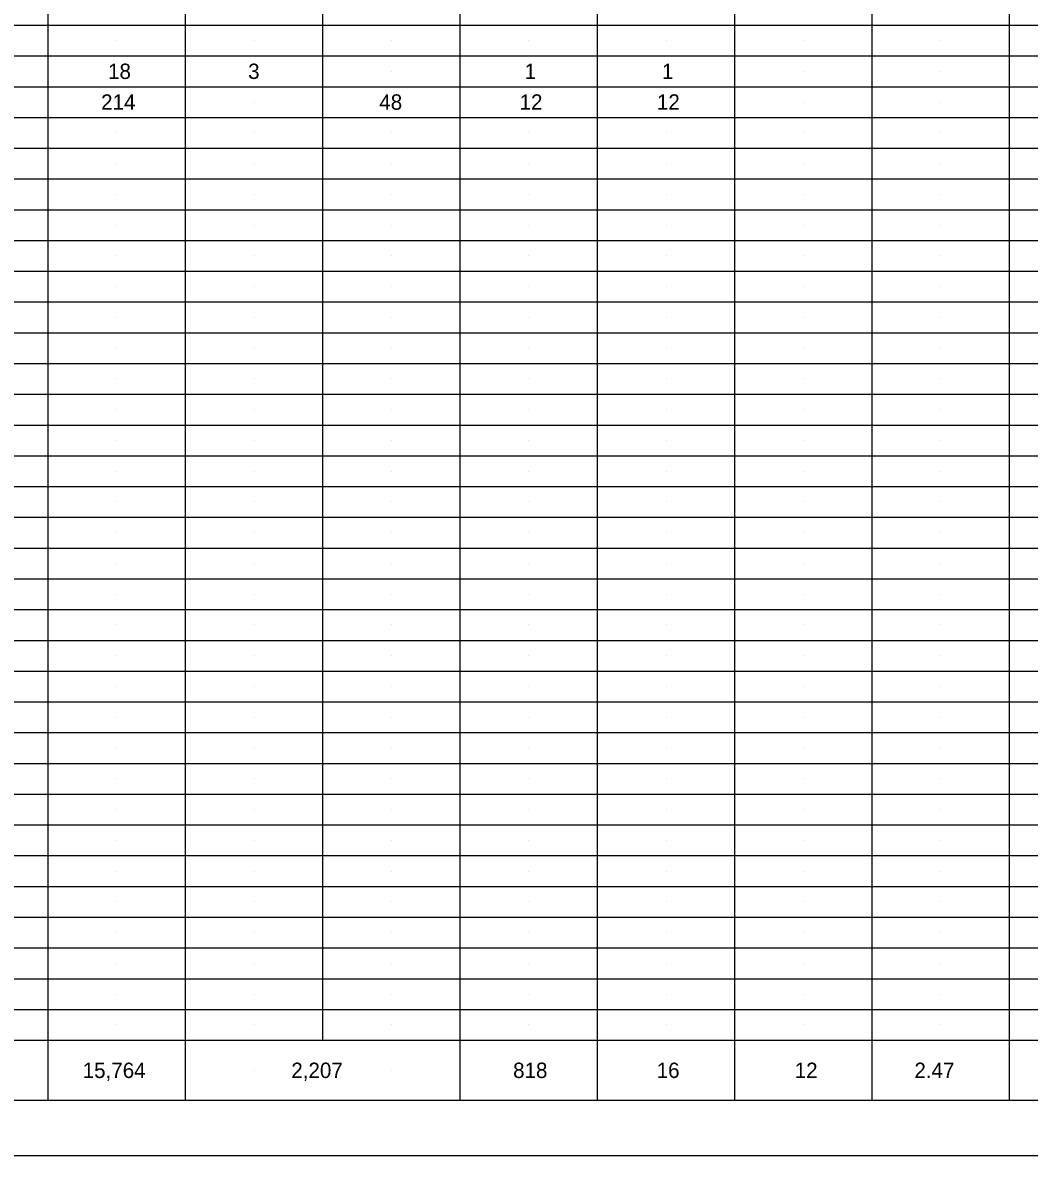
# Model space of a CAD drawing. Extents: x 2107022.8 to 2107056.8, y 706071 to 706093.
# Drawn here: x 2107038.83 to 2107047.99, y 706070.99 to 706081.3 of the extents above; entities that cross this region are included whole.
import ezdxf

# ---------------------------------------------------------------- set-up
doc = ezdxf.new("R2010")
doc.units = 0
for name, color, linetype in [('SC_Scratch1', 7, 'Continuous'), ('SH_Border', 7, 'Continuous'), ('SH_Cut_Line', 7, 'Continuous'), ('SH_Data', 7, 'Continuous'), ('SH_Text', 7, 'Continuous')]:
    doc.layers.add(name, color=color, linetype=linetype)

msp = doc.modelspace()

# ---------------------------------------------------------------- linework, layer by layer
at = {"layer": 'SC_Scratch1'}
for p, q in [((2107039.687, 706081.135), (2107039.687, 706081.135)), ((2107040.937, 706081.135), (2107040.937, 706081.135)), ((2107042.187, 706081.135), (2107042.187, 706081.135)), ((2107043.437, 706081.135), (2107043.437, 706081.135)), ((2107044.687, 706081.135), (2107044.687, 706081.135)), ((2107045.937, 706081.135), (2107045.937, 706081.135)), ((2107047.187, 706081.135), (2107047.187, 706081.135)), ((2107039.687, 706080.855), (2107039.687, 706080.855)), ((2107040.937, 706080.855), (2107040.937, 706080.855)), ((2107042.187, 706080.855), (2107042.187, 706080.855)), ((2107043.437, 706080.855), (2107043.437, 706080.855)), ((2107044.687, 706080.855), (2107044.687, 706080.855)), ((2107045.937, 706080.855), (2107045.937, 706080.855)), ((2107047.187, 706080.855), (2107047.187, 706080.855)), ((2107039.687, 706080.575), (2107039.687, 706080.575)), ((2107040.937, 706080.575), (2107040.937, 706080.575)), ((2107042.187, 706080.575), (2107042.187, 706080.575)), ((2107043.437, 706080.575), (2107043.437, 706080.575)), ((2107044.687, 706080.575), (2107044.687, 706080.575)), ((2107045.937, 706080.575), (2107045.937, 706080.575)), ((2107047.187, 706080.575), (2107047.187, 706080.575)), ((2107039.687, 706080.295), (2107039.687, 706080.295)), ((2107040.937, 706080.295), (2107040.937, 706080.295)), ((2107042.187, 706080.295), (2107042.187, 706080.295)), ((2107043.437, 706080.295), (2107043.437, 706080.295)), ((2107044.687, 706080.295), (2107044.687, 706080.295)), ((2107045.937, 706080.295), (2107045.937, 706080.295)), ((2107047.187, 706080.295), (2107047.187, 706080.295)), ((2107039.687, 706080.015), (2107039.687, 706080.015)), ((2107040.937, 706080.015), (2107040.937, 706080.015)), ((2107042.187, 706080.015), (2107042.187, 706080.015)), ((2107043.437, 706080.015), (2107043.437, 706080.015)), ((2107044.687, 706080.015), (2107044.687, 706080.015)), ((2107045.937, 706080.015), (2107045.937, 706080.015)), ((2107047.187, 706080.015), (2107047.187, 706080.015)), ((2107039.687, 706079.735), (2107039.687, 706079.735)), ((2107040.937, 706079.735), (2107040.937, 706079.735)), ((2107042.187, 706079.735), (2107042.187, 706079.735)), ((2107043.437, 706079.735), (2107043.437, 706079.735)), ((2107044.687, 706079.735), (2107044.687, 706079.735)), ((2107045.937, 706079.735), (2107045.937, 706079.735)), ((2107047.187, 706079.735), (2107047.187, 706079.735)), ((2107039.687, 706079.455), (2107039.687, 706079.455)), ((2107040.937, 706079.455), (2107040.937, 706079.455)), ((2107042.187, 706079.455), (2107042.187, 706079.455)), ((2107043.437, 706079.455), (2107043.437, 706079.455)), ((2107044.687, 706079.455), (2107044.687, 706079.455)), ((2107045.937, 706079.455), (2107045.937, 706079.455)), ((2107047.187, 706079.455), (2107047.187, 706079.455)), ((2107039.687, 706079.175), (2107039.687, 706079.175)), ((2107040.937, 706079.175), (2107040.937, 706079.175)), ((2107042.187, 706079.175), (2107042.187, 706079.175)), ((2107043.437, 706079.175), (2107043.437, 706079.175)), ((2107044.687, 706079.175), (2107044.687, 706079.175)), ((2107045.937, 706079.175), (2107045.937, 706079.175)), ((2107047.187, 706079.175), (2107047.187, 706079.175)), ((2107039.687, 706078.895), (2107039.687, 706078.895)), ((2107040.937, 706078.895), (2107040.937, 706078.895)), ((2107042.187, 706078.895), (2107042.187, 706078.895)), ((2107043.437, 706078.895), (2107043.437, 706078.895)), ((2107044.687, 706078.895), (2107044.687, 706078.895)), ((2107045.937, 706078.895), (2107045.937, 706078.895)), ((2107047.187, 706078.895), (2107047.187, 706078.895)), ((2107039.687, 706078.615), (2107039.687, 706078.615)), ((2107040.937, 706078.615), (2107040.937, 706078.615)), ((2107042.187, 706078.615), (2107042.187, 706078.615)), ((2107043.437, 706078.615), (2107043.437, 706078.615)), ((2107044.687, 706078.615), (2107044.687, 706078.615)), ((2107045.937, 706078.615), (2107045.937, 706078.615)), ((2107047.187, 706078.615), (2107047.187, 706078.615)), ((2107039.687, 706078.335), (2107039.687, 706078.335)), ((2107040.937, 706078.335), (2107040.937, 706078.335)), ((2107042.187, 706078.335), (2107042.187, 706078.335)), ((2107043.437, 706078.335), (2107043.437, 706078.335)), ((2107044.687, 706078.335), (2107044.687, 706078.335)), ((2107045.937, 706078.335), (2107045.937, 706078.335)), ((2107047.187, 706078.335), (2107047.187, 706078.335)), ((2107039.687, 706078.055), (2107039.687, 706078.055)), ((2107040.937, 706078.055), (2107040.937, 706078.055)), ((2107042.187, 706078.055), (2107042.187, 706078.055)), ((2107043.437, 706078.055), (2107043.437, 706078.055)), ((2107044.687, 706078.055), (2107044.687, 706078.055)), ((2107045.937, 706078.055), (2107045.937, 706078.055)), ((2107047.187, 706078.055), (2107047.187, 706078.055)), ((2107039.687, 706077.775), (2107039.687, 706077.775)), ((2107040.937, 706077.775), (2107040.937, 706077.775)), ((2107042.187, 706077.775), (2107042.187, 706077.775)), ((2107043.437, 706077.775), (2107043.437, 706077.775)), ((2107044.687, 706077.775), (2107044.687, 706077.775)), ((2107045.937, 706077.775), (2107045.937, 706077.775)), ((2107047.187, 706077.775), (2107047.187, 706077.775)), ((2107039.687, 706077.495), (2107039.687, 706077.495)), ((2107040.937, 706077.495), (2107040.937, 706077.495)), ((2107042.187, 706077.495), (2107042.187, 706077.495)), ((2107043.437, 706077.495), (2107043.437, 706077.495)), ((2107044.687, 706077.495), (2107044.687, 706077.495)), ((2107045.937, 706077.495), (2107045.937, 706077.495)), ((2107047.187, 706077.495), (2107047.187, 706077.495)), ((2107039.687, 706077.215), (2107039.687, 706077.215)), ((2107040.937, 706077.215), (2107040.937, 706077.215)), ((2107042.187, 706077.215), (2107042.187, 706077.215)), ((2107043.437, 706077.215), (2107043.437, 706077.215)), ((2107044.687, 706077.215), (2107044.687, 706077.215)), ((2107045.937, 706077.215), (2107045.937, 706077.215)), ((2107047.187, 706077.215), (2107047.187, 706077.215)), ((2107039.687, 706076.935), (2107039.687, 706076.935)), ((2107039.687, 706076.935), (2107039.687, 706076.935)), ((2107040.937, 706076.935), (2107040.937, 706076.935)), ((2107040.937, 706076.935), (2107040.937, 706076.935)), ((2107042.187, 706076.935), (2107042.187, 706076.935)), ((2107042.187, 706076.935), (2107042.187, 706076.935)), ((2107043.437, 706076.935), (2107043.437, 706076.935)), ((2107043.437, 706076.935), (2107043.437, 706076.935)), ((2107044.687, 706076.935), (2107044.687, 706076.935)), ((2107044.687, 706076.935), (2107044.687, 706076.935)), ((2107045.937, 706076.935), (2107045.937, 706076.935)), ((2107045.937, 706076.935), (2107045.937, 706076.935)), ((2107047.187, 706076.935), (2107047.187, 706076.935)), ((2107047.187, 706076.935), (2107047.187, 706076.935)), ((2107039.687, 706076.655), (2107039.687, 706076.655)), ((2107040.937, 706076.655), (2107040.937, 706076.655)), ((2107042.187, 706076.655), (2107042.187, 706076.655)), ((2107043.437, 706076.655), (2107043.437, 706076.655)), ((2107044.687, 706076.655), (2107044.687, 706076.655)), ((2107045.937, 706076.655), (2107045.937, 706076.655)), ((2107047.187, 706076.655), (2107047.187, 706076.655)), ((2107039.687, 706076.375), (2107039.687, 706076.375)), ((2107040.937, 706076.375), (2107040.937, 706076.375)), ((2107042.187, 706076.375), (2107042.187, 706076.375)), ((2107043.437, 706076.375), (2107043.437, 706076.375)), ((2107044.687, 706076.375), (2107044.687, 706076.375)), ((2107045.937, 706076.375), (2107045.937, 706076.375)), ((2107047.187, 706076.375), (2107047.187, 706076.375)), ((2107039.687, 706076.095), (2107039.687, 706076.095)), ((2107040.937, 706076.095), (2107040.937, 706076.095)), ((2107042.187, 706076.095), (2107042.187, 706076.095)), ((2107043.437, 706076.095), (2107043.437, 706076.095)), ((2107044.687, 706076.095), (2107044.687, 706076.095)), ((2107045.937, 706076.095), (2107045.937, 706076.095)), ((2107047.187, 706076.095), (2107047.187, 706076.095)), ((2107039.687, 706075.815), (2107039.687, 706075.815)), ((2107040.937, 706075.815), (2107040.937, 706075.815)), ((2107042.187, 706075.815), (2107042.187, 706075.815)), ((2107043.437, 706075.815), (2107043.437, 706075.815)), ((2107044.687, 706075.815), (2107044.687, 706075.815)), ((2107045.937, 706075.815), (2107045.937, 706075.815)), ((2107047.187, 706075.815), (2107047.187, 706075.815)), ((2107039.687, 706075.535), (2107039.687, 706075.535)), ((2107040.937, 706075.535), (2107040.937, 706075.535)), ((2107042.187, 706075.535), (2107042.187, 706075.535)), ((2107043.437, 706075.535), (2107043.437, 706075.535)), ((2107044.687, 706075.535), (2107044.687, 706075.535)), ((2107045.937, 706075.535), (2107045.937, 706075.535)), ((2107047.187, 706075.535), (2107047.187, 706075.535)), ((2107039.687, 706075.255), (2107039.687, 706075.255)), ((2107040.937, 706075.255), (2107040.937, 706075.255)), ((2107042.187, 706075.255), (2107042.187, 706075.255)), ((2107043.437, 706075.255), (2107043.437, 706075.255)), ((2107044.687, 706075.255), (2107044.687, 706075.255)), ((2107045.937, 706075.255), (2107045.937, 706075.255)), ((2107047.187, 706075.255), (2107047.187, 706075.255)), ((2107039.687, 706074.975), (2107039.687, 706074.975)), ((2107039.687, 706074.975), (2107039.687, 706074.975)), ((2107040.937, 706074.975), (2107040.937, 706074.975)), ((2107040.937, 706074.975), (2107040.937, 706074.975)), ((2107042.187, 706074.975), (2107042.187, 706074.975)), ((2107042.187, 706074.975), (2107042.187, 706074.975)), ((2107043.437, 706074.975), (2107043.437, 706074.975)), ((2107043.437, 706074.975), (2107043.437, 706074.975)), ((2107044.687, 706074.975), (2107044.687, 706074.975)), ((2107044.687, 706074.975), (2107044.687, 706074.975)), ((2107045.937, 706074.975), (2107045.937, 706074.975)), ((2107045.937, 706074.975), (2107045.937, 706074.975)), ((2107047.187, 706074.975), (2107047.187, 706074.975)), ((2107047.187, 706074.975), (2107047.187, 706074.975)), ((2107039.687, 706074.695), (2107039.687, 706074.695)), ((2107040.937, 706074.695), (2107040.937, 706074.695)), ((2107042.187, 706074.695), (2107042.187, 706074.695)), ((2107043.437, 706074.695), (2107043.437, 706074.695)), ((2107044.687, 706074.695), (2107044.687, 706074.695)), ((2107045.937, 706074.695), (2107045.937, 706074.695)), ((2107047.187, 706074.695), (2107047.187, 706074.695)), ((2107039.687, 706074.415), (2107039.687, 706074.415)), ((2107040.937, 706074.415), (2107040.937, 706074.415)), ((2107042.187, 706074.415), (2107042.187, 706074.415)), ((2107043.437, 706074.415), (2107043.437, 706074.415)), ((2107044.687, 706074.415), (2107044.687, 706074.415)), ((2107045.937, 706074.415), (2107045.937, 706074.415)), ((2107047.187, 706074.415), (2107047.187, 706074.415)), ((2107039.687, 706074.135), (2107039.687, 706074.135)), ((2107040.937, 706074.135), (2107040.937, 706074.135)), ((2107042.187, 706074.135), (2107042.187, 706074.135)), ((2107043.437, 706074.135), (2107043.437, 706074.135)), ((2107044.687, 706074.135), (2107044.687, 706074.135)), ((2107045.937, 706074.135), (2107045.937, 706074.135)), ((2107047.187, 706074.135), (2107047.187, 706074.135)), ((2107039.687, 706073.855), (2107039.687, 706073.855)), ((2107039.687, 706073.855), (2107039.687, 706073.855)), ((2107040.937, 706073.855), (2107040.937, 706073.855)), ((2107040.937, 706073.855), (2107040.937, 706073.855)), ((2107042.187, 706073.855), (2107042.187, 706073.855)), ((2107042.187, 706073.855), (2107042.187, 706073.855)), ((2107043.437, 706073.855), (2107043.437, 706073.855)), ((2107043.437, 706073.855), (2107043.437, 706073.855)), ((2107044.687, 706073.855), (2107044.687, 706073.855)), ((2107044.687, 706073.855), (2107044.687, 706073.855)), ((2107045.937, 706073.855), (2107045.937, 706073.855)), ((2107045.937, 706073.855), (2107045.937, 706073.855)), ((2107047.187, 706073.855), (2107047.187, 706073.855)), ((2107047.187, 706073.855), (2107047.187, 706073.855)), ((2107039.687, 706073.575), (2107039.687, 706073.575)), ((2107039.687, 706073.575), (2107039.687, 706073.575)), ((2107040.937, 706073.575), (2107040.937, 706073.575)), ((2107040.937, 706073.575), (2107040.937, 706073.575)), ((2107042.187, 706073.575), (2107042.187, 706073.575)), ((2107042.187, 706073.575), (2107042.187, 706073.575)), ((2107043.437, 706073.575), (2107043.437, 706073.575)), ((2107043.437, 706073.575), (2107043.437, 706073.575)), ((2107044.687, 706073.575), (2107044.687, 706073.575)), ((2107044.687, 706073.575), (2107044.687, 706073.575)), ((2107045.937, 706073.575), (2107045.937, 706073.575)), ((2107045.937, 706073.575), (2107045.937, 706073.575)), ((2107047.187, 706073.575), (2107047.187, 706073.575)), ((2107047.187, 706073.575), (2107047.187, 706073.575)), ((2107039.687, 706073.295), (2107039.687, 706073.295)), ((2107039.687, 706073.295), (2107039.687, 706073.295)), ((2107040.937, 706073.295), (2107040.937, 706073.295)), ((2107040.937, 706073.295), (2107040.937, 706073.295)), ((2107042.187, 706073.295), (2107042.187, 706073.295)), ((2107042.187, 706073.295), (2107042.187, 706073.295)), ((2107043.437, 706073.295), (2107043.437, 706073.295)), ((2107043.437, 706073.295), (2107043.437, 706073.295)), ((2107044.687, 706073.295), (2107044.687, 706073.295)), ((2107044.687, 706073.295), (2107044.687, 706073.295)), ((2107045.937, 706073.295), (2107045.937, 706073.295)), ((2107045.937, 706073.295), (2107045.937, 706073.295)), ((2107047.187, 706073.295), (2107047.187, 706073.295)), ((2107047.187, 706073.295), (2107047.187, 706073.295)), ((2107039.687, 706073.015), (2107039.687, 706073.015)), ((2107039.687, 706073.015), (2107039.687, 706073.015)), ((2107040.937, 706073.015), (2107040.937, 706073.015)), ((2107040.937, 706073.015), (2107040.937, 706073.015)), ((2107042.187, 706073.015), (2107042.187, 706073.015)), ((2107042.187, 706073.015), (2107042.187, 706073.015)), ((2107043.437, 706073.015), (2107043.437, 706073.015)), ((2107043.437, 706073.015), (2107043.437, 706073.015)), ((2107044.687, 706073.015), (2107044.687, 706073.015)), ((2107044.687, 706073.015), (2107044.687, 706073.015)), ((2107045.937, 706073.015), (2107045.937, 706073.015)), ((2107045.937, 706073.015), (2107045.937, 706073.015)), ((2107047.187, 706073.015), (2107047.187, 706073.015)), ((2107047.187, 706073.015), (2107047.187, 706073.015)), ((2107039.687, 706072.735), (2107039.687, 706072.735)), ((2107039.687, 706072.735), (2107039.687, 706072.735)), ((2107040.937, 706072.735), (2107040.937, 706072.735)), ((2107040.937, 706072.735), (2107040.937, 706072.735)), ((2107042.187, 706072.735), (2107042.187, 706072.735)), ((2107042.187, 706072.735), (2107042.187, 706072.735)), ((2107043.437, 706072.735), (2107043.437, 706072.735)), ((2107043.437, 706072.735), (2107043.437, 706072.735)), ((2107044.687, 706072.735), (2107044.687, 706072.735)), ((2107044.687, 706072.735), (2107044.687, 706072.735)), ((2107045.937, 706072.735), (2107045.937, 706072.735)), ((2107045.937, 706072.735), (2107045.937, 706072.735)), ((2107047.187, 706072.735), (2107047.187, 706072.735)), ((2107047.187, 706072.735), (2107047.187, 706072.735)), ((2107039.687, 706072.455), (2107039.687, 706072.455)), ((2107039.687, 706072.455), (2107039.687, 706072.455)), ((2107040.937, 706072.455), (2107040.937, 706072.455)), ((2107040.937, 706072.455), (2107040.937, 706072.455)), ((2107042.187, 706072.455), (2107042.187, 706072.455)), ((2107042.187, 706072.455), (2107042.187, 706072.455)), ((2107043.437, 706072.455), (2107043.437, 706072.455)), ((2107043.437, 706072.455), (2107043.437, 706072.455)), ((2107044.687, 706072.455), (2107044.687, 706072.455)), ((2107044.687, 706072.455), (2107044.687, 706072.455)), ((2107045.937, 706072.455), (2107045.937, 706072.455)), ((2107045.937, 706072.455), (2107045.937, 706072.455)), ((2107047.187, 706072.455), (2107047.187, 706072.455)), ((2107047.187, 706072.455), (2107047.187, 706072.455)), ((2107039.687, 706072.175), (2107039.687, 706072.175)), ((2107039.687, 706072.175), (2107039.687, 706072.175)), ((2107040.937, 706072.175), (2107040.937, 706072.175)), ((2107040.937, 706072.175), (2107040.937, 706072.175)), ((2107042.187, 706072.175), (2107042.187, 706072.175)), ((2107042.187, 706072.175), (2107042.187, 706072.175)), ((2107043.437, 706072.175), (2107043.437, 706072.175)), ((2107043.437, 706072.175), (2107043.437, 706072.175)), ((2107044.687, 706072.175), (2107044.687, 706072.175)), ((2107044.687, 706072.175), (2107044.687, 706072.175)), ((2107045.937, 706072.175), (2107045.937, 706072.175)), ((2107045.937, 706072.175), (2107045.937, 706072.175)), ((2107047.187, 706072.175), (2107047.187, 706072.175)), ((2107047.187, 706072.175), (2107047.187, 706072.175)), ((2107039.687, 706071.761), (2107039.687, 706071.761)), ((2107040.937, 706071.761), (2107040.937, 706071.761)), ((2107042.187, 706071.761), (2107042.187, 706071.761)), ((2107043.437, 706071.761), (2107043.437, 706071.761)), ((2107044.687, 706071.761), (2107044.687, 706071.761)), ((2107045.937, 706071.761), (2107045.937, 706071.761)), ((2107047.187, 706071.761), (2107047.187, 706071.761))]:
    msp.add_line(p, q, dxfattribs=at)
at = {"layer": 'SH_Border'}
msp.add_lwpolyline([(2107024.812, 706092.487), (2107056.312, 706092.487), (2107056.312, 706071.487), (2107024.812, 706071.487)], close=True, dxfattribs=at)
at = {"layer": 'SH_Cut_Line'}
msp.add_lwpolyline([(2107022.812, 706070.987), (2107056.812, 706070.987), (2107056.812, 706092.987), (2107022.812, 706092.987)], close=True, dxfattribs=at)
at = {"layer": 'SH_Data'}
for p, q in [((2107039.062, 706071.487), (2107039.062, 706092.487)), ((2107040.312, 706071.487), (2107040.312, 706092.487)), ((2107041.562, 706072.035), (2107041.562, 706092.487)), ((2107042.812, 706071.487), (2107042.812, 706092.487)), ((2107044.062, 706071.487), (2107044.062, 706092.487)), ((2107045.312, 706071.487), (2107045.312, 706092.487)), ((2107046.562, 706071.487), (2107046.562, 706092.487)), ((2107047.812, 706071.487), (2107047.812, 706092.487)), ((2107024.812, 706081.275), (2107055.312, 706081.275)), ((2107024.812, 706080.995), (2107055.312, 706080.995)), ((2107024.812, 706080.715), (2107055.312, 706080.715)), ((2107024.812, 706080.435), (2107055.312, 706080.435)), ((2107024.812, 706080.155), (2107055.312, 706080.155)), ((2107024.812, 706079.875), (2107055.312, 706079.875)), ((2107024.812, 706079.595), (2107055.312, 706079.595)), ((2107024.812, 706079.315), (2107055.312, 706079.315)), ((2107024.812, 706079.035), (2107055.312, 706079.035)), ((2107024.812, 706078.755), (2107055.312, 706078.755)), ((2107024.812, 706078.475), (2107055.312, 706078.475)), ((2107024.812, 706078.195), (2107055.312, 706078.195)), ((2107024.812, 706077.915), (2107055.312, 706077.915)), ((2107024.812, 706077.635), (2107055.312, 706077.635)), ((2107024.812, 706077.355), (2107055.312, 706077.355)), ((2107024.812, 706077.075), (2107055.312, 706077.075)), ((2107024.812, 706076.795), (2107055.312, 706076.795)), ((2107024.812, 706076.515), (2107055.312, 706076.515)), ((2107024.812, 706076.235), (2107055.312, 706076.235)), ((2107024.812, 706075.955), (2107055.312, 706075.955)), ((2107024.812, 706075.675), (2107055.312, 706075.675)), ((2107024.812, 706075.395), (2107055.312, 706075.395)), ((2107024.812, 706075.115), (2107055.312, 706075.115)), ((2107024.812, 706074.835), (2107055.312, 706074.835)), ((2107024.812, 706074.555), (2107055.312, 706074.555)), ((2107024.812, 706074.275), (2107055.312, 706074.275)), ((2107024.812, 706073.995), (2107055.312, 706073.995)), ((2107024.812, 706073.715), (2107055.312, 706073.715)), ((2107024.812, 706073.435), (2107055.312, 706073.435)), ((2107024.812, 706073.155), (2107055.312, 706073.155)), ((2107024.812, 706072.875), (2107055.312, 706072.875)), ((2107024.812, 706072.595), (2107055.312, 706072.595)), ((2107024.812, 706072.315), (2107055.312, 706072.315)), ((2107024.812, 706072.035), (2107055.312, 706072.035))]:
    msp.add_line(p, q, dxfattribs=at)

# ---------------------------------------------------------------- texts
at = {"layer": 'SH_Text'}
for s, p in [('18', (2107039.606, 706080.785)), ('3', (2107040.881, 706080.785)), ('1', (2107043.398, 706080.785)), ('1', (2107044.648, 706080.785)), ('214', (2107039.543, 706080.505)), ('48', (2107042.075, 706080.505)), ('12', (2107043.352, 706080.505)), ('12', (2107044.602, 706080.505)), ('15,764', (2107039.375, 706071.691)), ('2,207', (2107041.274, 706071.691)), ('818', (2107043.293, 706071.691)), ('16', (2107044.6, 706071.691)), ('12', (2107045.856, 706071.691)), ('2.47', (2107046.946, 706071.691))]:
    msp.add_text(s, height=0.14, dxfattribs=at).set_placement(p)

doc.saveas('drawing.dxf')
